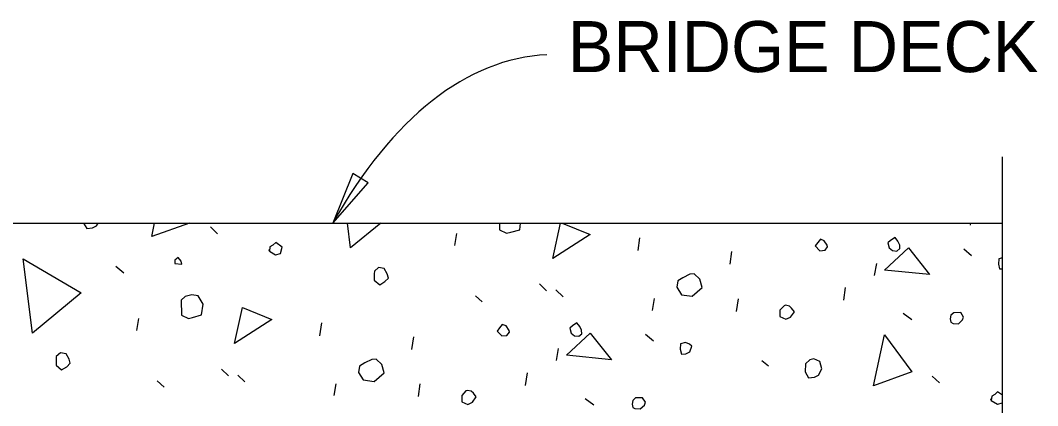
# Model space of a CAD drawing. Extents: x -1660015.2 to -1659984.9, y 2580594.2 to 2580616.7.
# Drawn here: x -1659997.457 to -1659994.445, y 2580603.515 to 2580604.656 of the extents above; entities that cross this region are included whole.
import ezdxf

# ---------------------------------------------------------------- set-up
doc = ezdxf.new("R2010")
doc.units = 0
for name, color, linetype in [('Miscellaneous', 7, 'Continuous'), ('Miscellaneous3', 7, 'Continuous'), ('PlotBorder_dp', 7, 'Continuous'), ('SheetLines_dp', 7, 'Continuous')]:
    doc.layers.add(name, color=color, linetype=linetype)

msp = doc.modelspace()

# ---------------------------------------------------------------- linework, layer by layer
at = {"layer": 'Miscellaneous'}
for p, q in [((-1659996.894, 2580604.0443), (-1659996.873, 2580604.0241)), ((-1659994.6436, 2580604.0494), (-1659994.6425, 2580604.056)), ((-1659996.1702, 2580603.9898), (-1659996.1641, 2580604.0251)), ((-1659995.6278, 2580603.9747), (-1659995.6224, 2580604.0124)), ((-1659994.6637, 2580603.9794), (-1659994.6403, 2580603.9597)), ((-1659995.3555, 2580603.9338), (-1659995.35, 2580603.9715)), ((-1659997.1734, 2580603.9281), (-1659997.1501, 2580603.9084)), ((-1659994.9274, 2580603.9009), (-1659994.9213, 2580603.9362)), ((-1659995.9197, 2580603.8758), (-1659995.8987, 2580603.8555)), ((-1659995.8709, 2580603.8578), (-1659995.8499, 2580603.8375)), ((-1659995.0189, 2580603.8272), (-1659995.0135, 2580603.8649)), ((-1659996.1095, 2580603.8404), (-1659996.0892, 2580603.8226)), ((-1659995.5854, 2580603.7971), (-1659995.5793, 2580603.8324)), ((-1659995.3361, 2580603.794), (-1659995.3307, 2580603.8317)), ((-1659997.112, 2580603.7375), (-1659997.1059, 2580603.7727)), ((-1659994.843, 2580603.789), (-1659994.8172, 2580603.77)), ((-1659996.5696, 2580603.7223), (-1659996.5642, 2580603.76)), ((-1659996.2972, 2580603.6814), (-1659996.2918, 2580603.7191)), ((-1659995.6055, 2580603.727), (-1659995.5821, 2580603.7074)), ((-1659995.8692, 2580603.6486), (-1659995.8631, 2580603.6839)), ((-1659995.2609, 2580603.6485), (-1659995.2412, 2580603.6331)), ((-1659996.8614, 2580603.6234), (-1659996.8405, 2580603.6032)), ((-1659997.0513, 2580603.5881), (-1659997.031, 2580603.5702)), ((-1659996.8126, 2580603.6054), (-1659996.7917, 2580603.5852)), ((-1659995.9607, 2580603.5749), (-1659995.9553, 2580603.6126)), ((-1659994.7568, 2580603.6024), (-1659994.7358, 2580603.5822)), ((-1659996.5272, 2580603.5447), (-1659996.5211, 2580603.58)), ((-1659996.2779, 2580603.5417), (-1659996.2725, 2580603.5794)), ((-1659995.7848, 2580603.5366), (-1659995.759, 2580603.5176))]:
    msp.add_line(p, q, dxfattribs=at)
for points in [[(-1659997.2694, 2580604.056), (-1659997.2602, 2580604.0394), (-1659997.2426, 2580604.0415), (-1659997.2312, 2580604.0472), (-1659997.2261, 2580604.056)], [(-1659997.0676, 2580604.0159), (-1659997.0591, 2580604.056)], [(-1659996.9562, 2580604.056), (-1659997.0676, 2580604.0159)], [(-1659996.4788, 2580603.9822), (-1659996.4881, 2580604.056)], [(-1659996.3893, 2580604.056), (-1659996.4788, 2580603.9822)], [(-1659996.0382, 2580604.056), (-1659996.0376, 2580604.0357), (-1659996.0168, 2580604.0257), (-1659996.0047, 2580604.029), (-1659995.9782, 2580604.0361), (-1659995.9755, 2580604.056)], [(-1659995.8803, 2580603.951), (-1659995.8577, 2580604.056)], [(-1659995.852, 2580604.056), (-1659995.7699, 2580604.022), (-1659995.8803, 2580603.951)], [(-1659995.1035, 2580603.9883), (-1659995.0893, 2580603.974), (-1659995.0742, 2580603.9755), (-1659995.0665, 2580603.9853), (-1659995.0677, 2580603.9902), (-1659995.0765, 2580604.0034), (-1659995.0881, 2580604.008), (-1659995.0958, 2580603.9982), (-1659995.1035, 2580603.9883)], [(-1659994.8845, 2580603.9823), (-1659994.8746, 2580603.9746), (-1659994.8613, 2580603.973), (-1659994.8529, 2580603.9804), (-1659994.8531, 2580603.9907), (-1659994.8587, 2580604.0022), (-1659994.8668, 2580604.0129), (-1659994.88, 2580604.0042), (-1659994.8884, 2580603.9968), (-1659994.8845, 2580603.9823)], [(-1659996.7193, 2580603.9721), (-1659996.701, 2580603.9615), (-1659996.6865, 2580603.9654), (-1659996.6814, 2580603.9848), (-1659996.7004, 2580603.9979), (-1659996.7087, 2580603.9904), (-1659996.7178, 2580603.9854), (-1659996.7193, 2580603.9721), (-1659996.7206, 2580603.9769)], [(-1659994.8979, 2580603.9166), (-1659994.8275, 2580603.9821), (-1659994.7649, 2580603.9031), (-1659994.8979, 2580603.9166)], [(-1659997.4205, 2580603.7298), (-1659997.4485, 2580603.9501), (-1659997.2764, 2580603.8487), (-1659997.4205, 2580603.7298)], [(-1659996.9995, 2580603.9358), (-1659996.9783, 2580603.9338), (-1659996.9808, 2580603.9434), (-1659996.9889, 2580603.9542), (-1659996.9997, 2580603.9461), (-1659996.9995, 2580603.9358)], [(-1659994.5491, 2580603.9531), (-1659994.5601, 2580603.9502), (-1659994.5611, 2580603.9344)], [(-1659996.4089, 2580603.9051), (-1659996.4092, 2580603.8869), (-1659996.3926, 2580603.8733), (-1659996.377, 2580603.8826), (-1659996.3669, 2580603.8931), (-1659996.3701, 2580603.9052), (-1659996.3795, 2580603.9208), (-1659996.3959, 2580603.9242), (-1659996.4085, 2580603.913), (-1659996.4089, 2580603.9051)], [(-1659994.5611, 2580603.9344), (-1659994.5572, 2580603.9199), (-1659994.5491, 2580603.9204)], [(-1659995.5132, 2580603.8656), (-1659995.4995, 2580603.8434), (-1659995.4673, 2580603.8391), (-1659995.438, 2580603.8651), (-1659995.4445, 2580603.8892), (-1659995.4617, 2580603.9053), (-1659995.4744, 2580603.9045), (-1659995.4949, 2580603.8938), (-1659995.5105, 2580603.8845), (-1659995.5132, 2580603.8656)], [(-1659996.9807, 2580603.827), (-1659996.9794, 2580603.7833), (-1659996.9586, 2580603.7734), (-1659996.9465, 2580603.7766), (-1659996.9199, 2580603.7837), (-1659996.9156, 2580603.816), (-1659996.93, 2580603.8406), (-1659996.9488, 2580603.8433), (-1659996.9682, 2580603.8381), (-1659996.9807, 2580603.827)], [(-1659996.8221, 2580603.6987), (-1659996.799, 2580603.8058), (-1659996.7117, 2580603.7697), (-1659996.8221, 2580603.6987)], [(-1659995.2076, 2580603.7974), (-1659995.2079, 2580603.7792), (-1659995.1902, 2580603.771), (-1659995.1764, 2580603.7773), (-1659995.1651, 2580603.7933), (-1659995.1732, 2580603.804), (-1659995.1799, 2580603.81), (-1659995.1909, 2580603.8122), (-1659995.1957, 2580603.8109), (-1659995.2076, 2580603.7974)], [(-1659994.7013, 2580603.7622), (-1659994.6951, 2580603.7587), (-1659994.6794, 2580603.7578), (-1659994.6668, 2580603.7689), (-1659994.6639, 2580603.7774), (-1659994.6726, 2580603.7906), (-1659994.6933, 2580603.7903), (-1659994.7016, 2580603.7829), (-1659994.7039, 2580603.7719), (-1659994.7013, 2580603.7622)], [(-1659996.0453, 2580603.736), (-1659996.0311, 2580603.7217), (-1659996.016, 2580603.7231), (-1659996.0082, 2580603.733), (-1659996.0095, 2580603.7378), (-1659996.0182, 2580603.751), (-1659996.0298, 2580603.7557), (-1659996.0376, 2580603.7458), (-1659996.0453, 2580603.736)], [(-1659995.8263, 2580603.73), (-1659995.8164, 2580603.7223), (-1659995.8031, 2580603.7207), (-1659995.7947, 2580603.7281), (-1659995.7949, 2580603.7384), (-1659995.8005, 2580603.7498), (-1659995.8086, 2580603.7606), (-1659995.8218, 2580603.7519), (-1659995.8301, 2580603.7445), (-1659995.8263, 2580603.73)], [(-1659995.8397, 2580603.6643), (-1659995.7692, 2580603.7297), (-1659995.7067, 2580603.6507), (-1659995.8397, 2580603.6643)], [(-1659994.9304, 2580603.574), (-1659994.8983, 2580603.725), (-1659994.817, 2580603.6148), (-1659994.9304, 2580603.574)], [(-1659995.5028, 2580603.6821), (-1659995.4989, 2580603.6676), (-1659995.4862, 2580603.6684), (-1659995.4748, 2580603.674), (-1659995.469, 2580603.6911), (-1659995.4758, 2580603.6971), (-1659995.4874, 2580603.7017), (-1659995.5019, 2580603.6978), (-1659995.5028, 2580603.6821)], [(-1659997.3507, 2580603.6528), (-1659997.351, 2580603.6346), (-1659997.3344, 2580603.6209), (-1659997.3188, 2580603.6303), (-1659997.3087, 2580603.6408), (-1659997.3119, 2580603.6528), (-1659997.3213, 2580603.6684), (-1659997.3377, 2580603.6718), (-1659997.3502, 2580603.6607), (-1659997.3507, 2580603.6528)], [(-1659996.455, 2580603.6133), (-1659996.4413, 2580603.5911), (-1659996.409, 2580603.5868), (-1659996.3798, 2580603.6127), (-1659996.3862, 2580603.6369), (-1659996.4035, 2580603.653), (-1659996.4162, 2580603.6521), (-1659996.4366, 2580603.6415), (-1659996.4523, 2580603.6321), (-1659996.455, 2580603.6133)], [(-1659995.1316, 2580603.6392), (-1659995.133, 2580603.6155), (-1659995.123, 2580603.5975), (-1659995.1054, 2580603.5996), (-1659995.094, 2580603.6052), (-1659995.0834, 2580603.6236), (-1659995.0892, 2580603.6453), (-1659995.107, 2580603.6535), (-1659995.119, 2580603.6503), (-1659995.1316, 2580603.6392)], [(-1659996.1494, 2580603.545), (-1659996.1497, 2580603.5268), (-1659996.132, 2580603.5186), (-1659996.1181, 2580603.5249), (-1659996.1069, 2580603.5409), (-1659996.1149, 2580603.5517), (-1659996.1217, 2580603.5576), (-1659996.1327, 2580603.5599), (-1659996.1375, 2580603.5586), (-1659996.1494, 2580603.545)], [(-1659994.5491, 2580603.5463), (-1659994.5632, 2580603.556), (-1659994.5715, 2580603.5485), (-1659994.5806, 2580603.5435), (-1659994.5821, 2580603.5302), (-1659994.5834, 2580603.535)], [(-1659995.6431, 2580603.5099), (-1659995.6369, 2580603.5064), (-1659995.6211, 2580603.5054), (-1659995.6086, 2580603.5165), (-1659995.6057, 2580603.5251), (-1659995.6144, 2580603.5383), (-1659995.635, 2580603.5379), (-1659995.6434, 2580603.5305), (-1659995.6456, 2580603.5196), (-1659995.6431, 2580603.5099)], [(-1659994.5821, 2580603.5302), (-1659994.5638, 2580603.5196), (-1659994.5493, 2580603.5234), (-1659994.5491, 2580603.5241)]]:
    msp.add_lwpolyline(points, dxfattribs=at)
at = {"layer": 'Miscellaneous3'}
msp.add_line((-1660001.5583, 2580604.056), (-1659994.5491, 2580604.056), dxfattribs=at)
at = {"layer": 'SheetLines_dp'}
msp.add_lwpolyline([(-1659994.5491, 2580602.799), (-1659994.5491, 2580604.252)], dxfattribs=at)
msp.add_lwpolyline([(-1659996.5314, 2580604.0559), (-1659996.4268, 2580604.1748), (-1659996.4718, 2580604.2026)], close=True, dxfattribs=at)
msp.add_ellipse((-1659995.7863, 2580602.1871), major_axis=(0.1111, -2.3674), ratio=0.464296, start_param=3.141604, end_param=3.781059, dxfattribs=at)

# ---------------------------------------------------------------- texts
at = {"layer": 'PlotBorder_dp'}
msp.add_text('BRIDGE DECK', height=0.1512, dxfattribs=at).set_placement((-1659995.8356, 2580604.5029))

doc.saveas('drawing.dxf')
